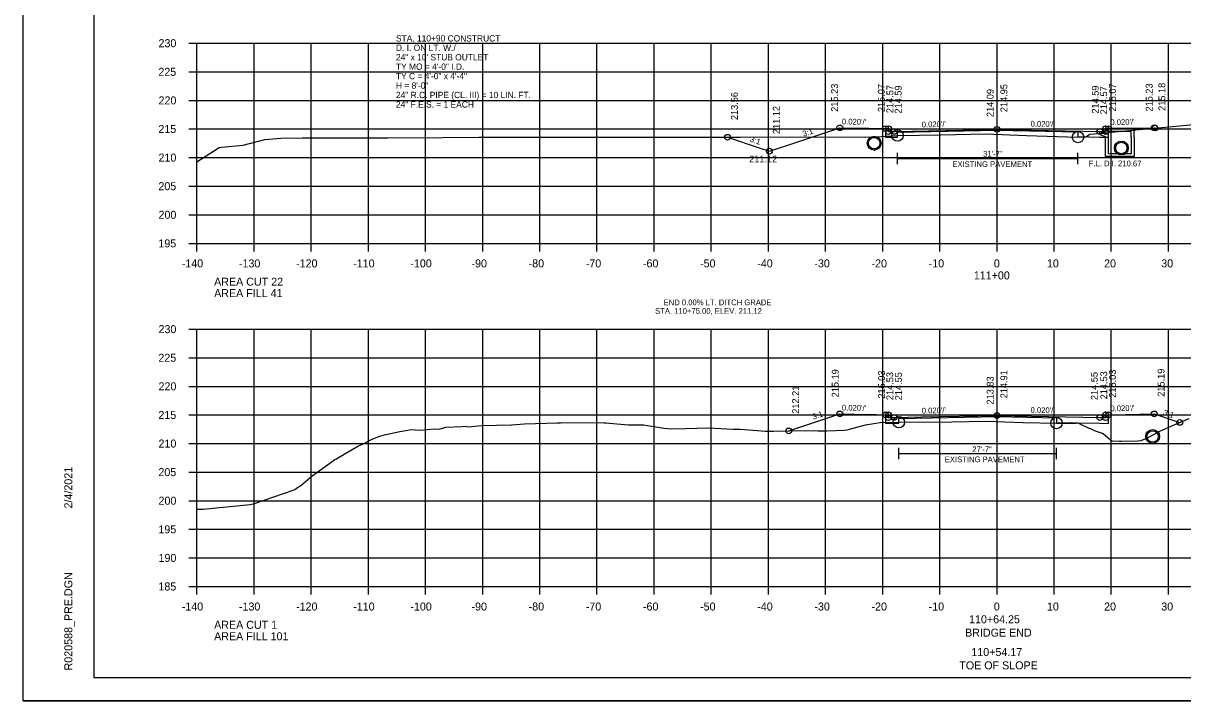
# Model space of a CAD drawing. Extents: x 1368968 to 1369915, y 377395 to 380381.
# Drawn here: x 1369581.4 to 1369784.3, y 377394.7 to 377513.2 of the extents above; entities that cross this region are included whole.
import ezdxf

# ---------------------------------------------------------------- set-up
doc = ezdxf.new("R2010")
doc.units = 0
for name, color, linetype in [('Default', 7, 'Continuous'), ('S_BORDER_NO_PLOT', 7, 'Continuous'), ('S_BREAKLINE_ANNOT', 7, 'Continuous'), ('S_BRIDGE', 7, 'Continuous'), ('S_BRIDGE_ANNOT', 7, 'Continuous'), ('S_CROSS_DRAIN', 7, 'Continuous'), ('S_CTL_TABLE', 7, 'Continuous'), ('S_CURB_ANNOT', 7, 'Continuous'), ('S_DITCHLINE_ANNOT', 7, 'Continuous'), ('S_DROP_INLET', 7, 'Continuous'), ('S_EXIST_ROW_ANNOT', 7, 'Continuous'), ('S_EXISTING_ALIGNMENT_ANNOT', 7, 'Continuous'), ('S_FENCE', 7, 'Continuous')]:
    doc.layers.add(name, color=color, linetype=linetype)

msp = doc.modelspace()

# ---------------------------------------------------------------- linework, layer by layer
at = {"layer": 'Default'}
msp.add_line((1369762.19, 377444.2), (1369762.19, 377443.37), dxfattribs=at)
at = {"layer": 'S_BORDER_NO_PLOT'}
for points in [[(1369732.27, 377494.74), (1369732.28, 377493.23), (1369733.78, 377493.26), (1369734.37, 377493.27), (1369734.37, 377494.1), (1369751.78, 377494.45), (1369765.95, 377494.17), (1369765.95, 377493.34), (1369769.78, 377493.26), (1369771.28, 377493.23), (1369771.29, 377494.74)], [(1369732.27, 377444.7), (1369732.28, 377443.19), (1369733.78, 377443.22), (1369734.61, 377443.24), (1369734.61, 377444.07), (1369751.78, 377444.41), (1369762.19, 377444.2), (1369762.19, 377443.37), (1369769.78, 377443.22), (1369771.28, 377443.19), (1369771.29, 377444.7)]]:
    msp.add_lwpolyline(points, dxfattribs=at)
at = {"layer": 'S_BREAKLINE_ANNOT'}
for p, q in [((1369610.38, 377509.68), (1369611.78, 377509.68)), ((1369611.78, 377474.68), (1369611.78, 377509.68)), ((1369610.38, 377504.68), (1369611.78, 377504.68)), ((1369610.38, 377499.68), (1369611.78, 377499.68)), ((1369610.38, 377494.68), (1369611.78, 377494.68)), ((1369610.38, 377489.68), (1369611.78, 377489.68)), ((1369610.38, 377484.68), (1369611.78, 377484.68)), ((1369610.38, 377479.68), (1369611.78, 377479.68)), ((1369610.38, 377474.68), (1369611.78, 377474.68)), ((1369611.78, 377474.68), (1369891.78, 377474.68)), ((1369611.78, 377473.28), (1369611.78, 377474.68)), ((1369621.78, 377473.28), (1369621.78, 377474.68)), ((1369631.78, 377473.28), (1369631.78, 377474.68)), ((1369641.78, 377473.28), (1369641.78, 377474.68)), ((1369651.78, 377473.28), (1369651.78, 377474.68)), ((1369661.78, 377473.28), (1369661.78, 377474.68)), ((1369671.78, 377473.28), (1369671.78, 377474.68)), ((1369681.78, 377473.28), (1369681.78, 377474.68)), ((1369691.78, 377473.28), (1369691.78, 377474.68)), ((1369701.78, 377473.28), (1369701.78, 377474.68)), ((1369711.78, 377473.28), (1369711.78, 377474.68)), ((1369721.78, 377473.28), (1369721.78, 377474.68)), ((1369731.78, 377473.28), (1369731.78, 377474.68)), ((1369741.78, 377473.28), (1369741.78, 377474.68)), ((1369751.78, 377473.28), (1369751.78, 377474.68)), ((1369761.78, 377473.28), (1369761.78, 377474.68)), ((1369771.78, 377473.28), (1369771.78, 377474.68)), ((1369781.78, 377473.28), (1369781.78, 377474.68)), ((1369610.38, 377459.68), (1369611.78, 377459.68)), ((1369611.78, 377414.68), (1369611.78, 377459.68)), ((1369610.38, 377454.68), (1369611.78, 377454.68)), ((1369610.38, 377449.68), (1369611.78, 377449.68)), ((1369610.38, 377444.68), (1369611.78, 377444.68)), ((1369610.38, 377439.68), (1369611.78, 377439.68)), ((1369610.38, 377434.68), (1369611.78, 377434.68)), ((1369610.38, 377429.68), (1369611.78, 377429.68)), ((1369610.38, 377424.68), (1369611.78, 377424.68)), ((1369610.38, 377419.68), (1369611.78, 377419.68)), ((1369610.38, 377414.68), (1369611.78, 377414.68)), ((1369611.78, 377414.68), (1369891.78, 377414.68)), ((1369611.78, 377413.28), (1369611.78, 377414.68)), ((1369621.78, 377413.28), (1369621.78, 377414.68)), ((1369631.78, 377413.28), (1369631.78, 377414.68)), ((1369641.78, 377413.28), (1369641.78, 377414.68)), ((1369651.78, 377413.28), (1369651.78, 377414.68)), ((1369661.78, 377413.28), (1369661.78, 377414.68)), ((1369671.78, 377413.28), (1369671.78, 377414.68)), ((1369681.78, 377413.28), (1369681.78, 377414.68)), ((1369691.78, 377413.28), (1369691.78, 377414.68)), ((1369701.78, 377413.28), (1369701.78, 377414.68)), ((1369711.78, 377413.28), (1369711.78, 377414.68)), ((1369721.78, 377413.28), (1369721.78, 377414.68)), ((1369731.78, 377413.28), (1369731.78, 377414.68)), ((1369741.78, 377413.28), (1369741.78, 377414.68)), ((1369751.78, 377413.28), (1369751.78, 377414.68)), ((1369761.78, 377413.28), (1369761.78, 377414.68)), ((1369771.78, 377413.28), (1369771.78, 377414.68)), ((1369781.78, 377413.28), (1369781.78, 377414.68))]:
    msp.add_line(p, q, dxfattribs=at)
at = {"layer": 'S_BRIDGE_ANNOT'}
for p, q in [((1369593.78, 377398.68), (1369593.78, 377604.14)), ((1369593.78, 377398.68), (1369593.78, 377398.68)), ((1369909.96, 377398.68), (1369593.78, 377398.68))]:
    msp.add_line(p, q, dxfattribs=at)
at = {"layer": 'S_CROSS_DRAIN'}
for p, q in [((1369734.37, 377489.54), (1369765.95, 377489.54)), ((1369734.61, 377437.92), (1369762.19, 377437.92))]:
    msp.add_line(p, q, dxfattribs=at)
at = {"layer": 'S_CTL_TABLE'}
for points in [[(1369611.78, 377488.96), (1369615.69, 377491.43), (1369616.05, 377491.49), (1369619.89, 377491.83), (1369623.65, 377492.85), (1369626.43, 377493.06), (1369630.2, 377493.16), (1369632.63, 377493.15), (1369645.18, 377493.15), (1369654.82, 377493.17), (1369661.13, 377493.23), (1369670.21, 377493.24), (1369678.08, 377493.26), (1369687.12, 377493.25), (1369692.65, 377493.27), (1369704.67, 377493.23), (1369705.31, 377493.23), (1369706.86, 377493.23), (1369717.38, 377493.29), (1369722.26, 377493.27), (1369728.66, 377493.32), (1369729.46, 377493.27), (1369730.67, 377493.32), (1369732.28, 377493.42), (1369734.37, 377493.54), (1369741.94, 377493.66), (1369749.73, 377493.86), (1369756.94, 377493.54), (1369765.95, 377493.27), (1369766.64, 377493.3), (1369767.39, 377493.33), (1369767.74, 377493.58), (1369768.01, 377493.8), (1369768.79, 377493.83), (1369779.09, 377494.82), (1369779.23, 377494.83), (1369779.37, 377494.85), (1369788.61, 377495.68)], [(1369611.78, 377428.21), (1369612.63, 377428.21), (1369612.68, 377428.21), (1369612.86, 377428.23), (1369621.08, 377428.99), (1369621.87, 377429.17), (1369628.61, 377431.53), (1369628.92, 377431.63), (1369629.35, 377431.97), (1369629.91, 377432.29), (1369631.92, 377434.04), (1369635.05, 377436.24), (1369635.9, 377436.9), (1369636.1, 377436.95), (1369637.81, 377437.97), (1369640.07, 377439.29), (1369640.62, 377439.49), (1369642.56, 377440.51), (1369643.8, 377440.99), (1369644.17, 377441.06), (1369644.6, 377441.21), (1369647.3, 377441.81), (1369648.67, 377442.03), (1369649.21, 377442.11), (1369650.84, 377442.03), (1369653.31, 377442.25), (1369654.15, 377442.22), (1369655.3, 377442.54), (1369658.2, 377442.65), (1369658.74, 377442.69), (1369659.24, 377442.62), (1369661.54, 377442.83), (1369666.84, 377442.97), (1369669.12, 377443.14), (1369674.85, 377443.28), (1369675.4, 377443.32), (1369675.72, 377443.35), (1369683.05, 377443.31), (1369683.31, 377443.31), (1369683.35, 377443.31), (1369687.26, 377442.93), (1369689.9, 377442.93), (1369693.5, 377442.37), (1369694.76, 377442.27), (1369697.27, 377442.31), (1369701.25, 377442.45), (1369705.62, 377442.21), (1369706.84, 377442.21), (1369711.28, 377441.87), (1369712.69, 377441.85), (1369718.31, 377441.93), (1369720.43, 377441.9), (1369722, 377441.89), (1369725.03, 377442), (1369725.55, 377442.08), (1369728.75, 377442.93), (1369731.68, 377443.41), (1369733.25, 377443.37), (1369734.61, 377443.4), (1369743.89, 377443.49), (1369749.88, 377443.57), (1369756.31, 377443.38), (1369762.19, 377443.26), (1369765.58, 377443.25), (1369765.95, 377443.27), (1369766.02, 377443.24), (1369766.15, 377443.16), (1369767.86, 377442.39), (1369767.93, 377442.35), (1369768.23, 377442.24), (1369768.8, 377441.98), (1369770.33, 377441.44), (1369771.24, 377440.66), (1369771.85, 377440.14), (1369772.01, 377440.15), (1369773.16, 377440.12), (1369773.58, 377440.11), (1369776.44, 377440.14), (1369777.02, 377440.2), (1369778.25, 377440.75), (1369780.28, 377441.82), (1369782.91, 377443.02), (1369785.4, 377444.06)]]:
    msp.add_lwpolyline(points, dxfattribs=at)
at = {"layer": 'S_CURB_ANNOT'}
for points in [[(1369704.63, 377493.23), (1369710.16, 377491.39), (1369711.95, 377490.8), (1369716.91, 377492.45), (1369724.27, 377494.9), (1369729.27, 377494.8), (1369732.27, 377494.74), (1369732.36, 377494.74), (1369732.77, 377494.74), (1369732.77, 377494.51), (1369732.78, 377494.24), (1369733.78, 377494.26), (1369751.78, 377494.62), (1369769.78, 377494.26), (1369770.78, 377494.24), (1369770.79, 377494.74), (1369770.89, 377494.74), (1369771.29, 377494.74), (1369774.29, 377494.8), (1369779.29, 377494.9), (1369779.36, 377494.88), (1369779.43, 377494.85)], [(1369715.34, 377441.89), (1369724.27, 377444.86), (1369729.27, 377444.76), (1369730.7, 377444.73), (1369732.27, 377444.7), (1369732.77, 377444.7), (1369732.78, 377444.2), (1369733.43, 377444.22), (1369733.78, 377444.22), (1369738.54, 377444.32), (1369751.78, 377444.58), (1369751.78, 377444.58), (1369769.78, 377444.22), (1369770.3, 377444.21), (1369770.78, 377444.2), (1369770.79, 377444.7), (1369771.29, 377444.7), (1369771.83, 377444.71), (1369774.29, 377444.76), (1369779.29, 377444.86), (1369783.75, 377443.37)]]:
    msp.add_lwpolyline(points, dxfattribs=at)
at = {"layer": 'S_DITCHLINE_ANNOT'}
for p, q in [((1369611.78, 377509.68), (1369891.78, 377509.68)), ((1369611.78, 377474.68), (1369611.78, 377509.68)), ((1369621.78, 377474.68), (1369621.78, 377509.68)), ((1369631.78, 377474.68), (1369631.78, 377509.68)), ((1369641.78, 377474.68), (1369641.78, 377509.68)), ((1369651.78, 377474.68), (1369651.78, 377509.68)), ((1369661.78, 377474.68), (1369661.78, 377509.68)), ((1369671.78, 377474.68), (1369671.78, 377509.68)), ((1369681.78, 377474.68), (1369681.78, 377509.68)), ((1369691.78, 377474.68), (1369691.78, 377509.68)), ((1369701.78, 377474.68), (1369701.78, 377509.68)), ((1369711.78, 377474.68), (1369711.78, 377509.68)), ((1369721.78, 377474.68), (1369721.78, 377509.68)), ((1369731.78, 377474.68), (1369731.78, 377509.68)), ((1369741.78, 377474.68), (1369741.78, 377509.68)), ((1369751.78, 377474.68), (1369751.78, 377509.68)), ((1369761.78, 377474.68), (1369761.78, 377509.68)), ((1369771.78, 377474.68), (1369771.78, 377509.68)), ((1369781.78, 377474.68), (1369781.78, 377509.68)), ((1369611.78, 377504.68), (1369891.78, 377504.68)), ((1369611.78, 377499.68), (1369891.78, 377499.68)), ((1369611.78, 377494.68), (1369891.78, 377494.68)), ((1369611.78, 377489.68), (1369891.78, 377489.68)), ((1369611.78, 377484.68), (1369891.78, 377484.68)), ((1369611.78, 377479.68), (1369891.78, 377479.68)), ((1369611.78, 377474.68), (1369891.78, 377474.68)), ((1369611.78, 377459.68), (1369891.78, 377459.68)), ((1369611.78, 377414.68), (1369611.78, 377459.68)), ((1369621.78, 377414.68), (1369621.78, 377459.68)), ((1369631.78, 377414.68), (1369631.78, 377459.68)), ((1369641.78, 377414.68), (1369641.78, 377459.68)), ((1369651.78, 377414.68), (1369651.78, 377459.68)), ((1369661.78, 377414.68), (1369661.78, 377459.68)), ((1369671.78, 377414.68), (1369671.78, 377459.68)), ((1369681.78, 377414.68), (1369681.78, 377459.68)), ((1369691.78, 377414.68), (1369691.78, 377459.68)), ((1369701.78, 377414.68), (1369701.78, 377459.68)), ((1369711.78, 377414.68), (1369711.78, 377459.68)), ((1369721.78, 377414.68), (1369721.78, 377459.68)), ((1369731.78, 377414.68), (1369731.78, 377459.68)), ((1369741.78, 377414.68), (1369741.78, 377459.68)), ((1369751.78, 377414.68), (1369751.78, 377459.68)), ((1369761.78, 377414.68), (1369761.78, 377459.68)), ((1369771.78, 377414.68), (1369771.78, 377459.68)), ((1369781.78, 377414.68), (1369781.78, 377459.68)), ((1369611.78, 377454.68), (1369891.78, 377454.68)), ((1369611.78, 377449.68), (1369891.78, 377449.68)), ((1369611.78, 377444.68), (1369891.78, 377444.68)), ((1369611.78, 377439.68), (1369891.78, 377439.68)), ((1369611.78, 377434.68), (1369891.78, 377434.68)), ((1369611.78, 377429.68), (1369891.78, 377429.68)), ((1369611.78, 377424.68), (1369891.78, 377424.68)), ((1369611.78, 377419.68), (1369891.78, 377419.68)), ((1369611.78, 377414.68), (1369891.78, 377414.68))]:
    msp.add_line(p, q, dxfattribs=at)
at = {"layer": 'S_DROP_INLET'}
for p, q in [((1369730.28, 377493.42), (1369730.28, 377493.26)), ((1369730.28, 377491), (1369730.28, 377490.85)), ((1369581.38, 377394.7), (1369914.71, 377394.7))]:
    msp.add_line(p, q, dxfattribs=at)
for points in [[(1369581.37, 377608.03), (1369914.71, 377608.03), (1369914.71, 377394.69), (1369581.37, 377394.69)], [(1369827.7, 377604.14), (1369827.7, 377594.26), (1369863.43, 377594.26), (1369863.43, 377591.34), (1369886.63, 377591.34), (1369886.63, 377567), (1369909.96, 377567), (1369909.96, 377398.68), (1369593.78, 377398.68), (1369593.78, 377604.14)]]:
    msp.add_lwpolyline(points, close=True, dxfattribs=at)
for centre, radius in [((1369724.27, 377494.9), 0.5), ((1369732.27, 377494.74), 0.5), ((1369732.77, 377494.74), 0.5), ((1369751.78, 377494.62), 0.5), ((1369770.79, 377494.74), 0.5), ((1369771.29, 377494.74), 0.5), ((1369779.29, 377494.9), 0.5), ((1369779.43, 377494.85), 0.5), ((1369704.63, 377493.23), 0.5), ((1369730.28, 377492.21), 1.21), ((1369732.78, 377494.24), 0.5), ((1369733.78, 377494.26), 0.5), ((1369733.78, 377494.26), 0.5), ((1369734.37, 377493.54), 1), ((1369765.95, 377493.27), 1), ((1369769.78, 377494.26), 0.5), ((1369769.78, 377494.26), 0.5), ((1369770.78, 377494.24), 0.5), ((1369711.95, 377490.8), 0.5), ((1369773.54, 377491.36), 1.21), ((1369724.27, 377444.86), 0.5), ((1369732.27, 377444.7), 0.5), ((1369732.77, 377444.7), 0.5), ((1369732.78, 377444.2), 0.5), ((1369733.78, 377444.22), 0.5), ((1369733.78, 377444.22), 0.5), ((1369734.61, 377443.4), 1), ((1369751.78, 377444.58), 0.5), ((1369769.78, 377444.22), 0.5), ((1369769.78, 377444.22), 0.5), ((1369770.78, 377444.2), 0.5), ((1369770.79, 377444.7), 0.5), ((1369771.29, 377444.7), 0.5), ((1369779.29, 377444.86), 0.5), ((1369715.34, 377441.89), 0.5), ((1369762.19, 377443.26), 1), ((1369783.75, 377443.37), 0.5), ((1369779.02, 377440.92), 1.21), ((1369779.02, 377440.92), 1)]:
    msp.add_circle(centre, radius, dxfattribs=at)
at = {"layer": 'S_EXIST_ROW_ANNOT'}
for p, q in [((1369730.28, 377493.21), (1369730.28, 377493.06)), ((1369769.78, 377494.27), (1369771.28, 377493.75)), ((1369769.78, 377493.74), (1369770.78, 377493.39)), ((1369770.78, 377493.25), (1369770.78, 377493.39)), ((1369770.94, 377494.58), (1369771.03, 377494.75)), ((1369770.94, 377494.58), (1369771.28, 377494.25)), ((1369775.78, 377494.75), (1369771.03, 377494.75)), ((1369775.28, 377494.25), (1369771.28, 377494.25)), ((1369771.28, 377493.25), (1369771.28, 377493.75)), ((1369775.28, 377493.25), (1369775.28, 377494.25)), ((1369775.78, 377493.25), (1369775.78, 377494.75)), ((1369730.28, 377491.21), (1369730.28, 377491.06)), ((1369734.37, 377488.54), (1369734.37, 377490.54)), ((1369765.95, 377488.54), (1369765.95, 377490.54)), ((1369734.61, 377436.92), (1369734.61, 377438.92)), ((1369762.19, 377436.92), (1369762.19, 377438.92))]:
    msp.add_line(p, q, dxfattribs=at)
for points in [[(1369769.78, 377493.74), (1369769.78, 377494.27)], [(1369775.78, 377493.25), (1369775.78, 377489.85), (1369773.28, 377489.85), (1369770.78, 377489.85), (1369770.78, 377493.25)], [(1369775.28, 377493.25), (1369775.28, 377490.35), (1369773.28, 377490.35), (1369771.28, 377490.35), (1369771.28, 377493.25)]]:
    msp.add_lwpolyline(points, dxfattribs=at)
for centre in [(1369730.28, 377492.21), (1369773.54, 377491.36)]:
    msp.add_circle(centre, 1, dxfattribs=at)
at = {"layer": 'S_EXISTING_ALIGNMENT_ANNOT'}
for p, q in [((1369751.78, 377493.77), (1369751.78, 377503.77)), ((1369751.78, 377443.51), (1369751.78, 377453.51))]:
    msp.add_line(p, q, dxfattribs=at)

# ---------------------------------------------------------------- texts
at = {"layer": 'Default'}
for s, p in [('STA. 110+90 CONSTRUCT', (1369646.6, 377509.98)), ('D. I. ON LT. W./', (1369646.6, 377508.33)), ('24" x 10\' STUB OUTLET ', (1369646.6, 377506.68)), ('TY MO = 4\'-0" I.D.', (1369646.6, 377505.03)), ('TY C = 4\'-0" x 4\'-4"', (1369646.6, 377503.38)), ('24" R.C. PIPE (CL. III) = 10 LIN. FT.', (1369646.6, 377500.08)), ('H = 8\'-0"', (1369646.6, 377501.73)), ('24" F.E.S. = 1 EACH', (1369646.6, 377498.43))]:
    msp.add_text(s, height=1.1, dxfattribs=at).set_placement(p)
at = {"layer": 'S_BRIDGE'}
for s, p in [('230', (1369605.05, 377508.98)), ('225', (1369605.03, 377503.98)), ('220', (1369605.05, 377498.98)), ('215', (1369605.03, 377493.98)), ('210', (1369605.05, 377488.98)), ('205', (1369605.03, 377483.98)), ('200', (1369605.05, 377478.98)), ('195', (1369605.03, 377473.98)), ('-140', (1369609.12, 377470.48)), ('-130', (1369619.12, 377470.48)), ('-120', (1369629.12, 377470.48)), ('-110', (1369639.12, 377470.48)), ('-100', (1369649.12, 377470.48)), ('-90', (1369659.82, 377470.48)), ('-80', (1369669.82, 377470.48)), ('-70', (1369679.82, 377470.48)), ('-60', (1369689.82, 377470.48)), ('-50', (1369699.82, 377470.48)), ('-40', (1369709.82, 377470.48)), ('-30', (1369719.82, 377470.48)), ('-20', (1369729.82, 377470.48)), ('-10', (1369739.82, 377470.48)), ('0', (1369751.22, 377470.48)), ('10', (1369760.52, 377470.48)), ('20', (1369770.52, 377470.48)), ('30', (1369780.52, 377470.48)), ('AREA CUT 22', (1369614.78, 377467.28)), ('111+00', (1369747.72, 377468.38)), ('AREA FILL 41', (1369614.78, 377465.28)), ('230', (1369605.05, 377458.98)), ('225', (1369605.03, 377453.98)), ('220', (1369605.05, 377448.98)), ('215', (1369605.03, 377443.98)), ('210', (1369605.05, 377438.98)), ('205', (1369605.03, 377433.98)), ('200', (1369605.05, 377428.98)), ('195', (1369605.03, 377423.98)), ('190', (1369605.05, 377418.98)), ('185', (1369605.03, 377413.98)), ('-140', (1369609.12, 377410.48)), ('-130', (1369619.12, 377410.48)), ('-120', (1369629.12, 377410.48)), ('-110', (1369639.12, 377410.48)), ('-100', (1369649.12, 377410.48)), ('-90', (1369659.82, 377410.48)), ('-80', (1369669.82, 377410.48)), ('-70', (1369679.82, 377410.48)), ('-60', (1369689.82, 377410.48)), ('-50', (1369699.82, 377410.48)), ('-40', (1369709.82, 377410.48)), ('-30', (1369719.82, 377410.48)), ('-20', (1369729.82, 377410.48)), ('-10', (1369739.82, 377410.48)), ('0', (1369751.22, 377410.48)), ('10', (1369760.52, 377410.48)), ('20', (1369770.52, 377410.48)), ('30', (1369780.52, 377410.48)), ('AREA CUT 1', (1369614.78, 377407.28)), ('110+64.25', (1369746.89, 377408.25)), ('AREA FILL 101', (1369614.78, 377405.28)), ('BRIDGE END', (1369746.19, 377405.91)), ('110+54.17', (1369747.29, 377402.52)), ('TOE OF SLOPE', (1369745.18, 377400.19))]:
    msp.add_text(s, height=1.4, dxfattribs=at).set_placement(p)
at = {"layer": 'S_BRIDGE_ANNOT'}
for s, p in [('2/4/2021', (1369589.97, 377428.32)), ('R020588_PRE.DGN', (1369589.97, 377400))]:
    msp.add_text(s, height=1.4, rotation=90, dxfattribs=at).set_placement(p)
at = {"layer": 'S_DROP_INLET'}
msp.add_text('+', height=0.1, dxfattribs=at).set_placement((1369778.97, 377439.87))
at = {"layer": 'S_EXIST_ROW_ANNOT'}
for s, height, p in [('211.12', 1.2, (1369708.41, 377488.83)), ('EXISTING PAVEMENT', 1, (1369743.96, 377488.03)), ('31\'-7"', 1, (1369749.34, 377489.84)), ('F.L. D.I. 210.67', 1, (1369767.84, 377488.16)), ('END 0.00% LT. DITCH GRADE', 1, (1369693.44, 377463.86)), ('STA. 110+75.00, ELEV. 211.12', 1, (1369691.95, 377462.36)), ('27\'-7"', 1, (1369747.46, 377438.17)), ('EXISTING PAVEMENT', 1, (1369742.64, 377436.41))]:
    msp.add_text(s, height=height, dxfattribs=at).set_placement(p)
at = {"layer": 'S_EXISTING_ALIGNMENT_ANNOT'}
for s, p in [('215.23', (1369723.95, 377497.69)), ('215.07', (1369732.13, 377497.64)), ('214.57', (1369733.64, 377497.45)), ('214.59', (1369735.09, 377497.38)), ('214.09', (1369751.18, 377496.77)), ('214.95', (1369753.58, 377497.62)), ('214.59', (1369769.58, 377497.37)), ('214.57', (1369771.05, 377497.24)), ('215.07', (1369772.59, 377497.74)), ('215.23', (1369779.01, 377497.74)), ('215.18', (1369781.23, 377497.85)), ('213.56', (1369706.43, 377496.23)), ('211.12', (1369713.75, 377493.8)), ('215.19', (1369724.07, 377447.76)), ('214.91', (1369753.58, 377447.58)), ('215.03', (1369772.59, 377447.7)), ('215.19', (1369781.09, 377447.86)), ('215.03', (1369732.18, 377447.53)), ('214.53', (1369733.63, 377447.27)), ('214.55', (1369735.14, 377447.24)), ('213.83', (1369751.18, 377446.51)), ('214.55', (1369769.4, 377447.28)), ('214.53', (1369771.06, 377447.41)), ('212.21', (1369717.14, 377444.89))]:
    msp.add_text(s, height=1.2, rotation=90, dxfattribs=at).set_placement(p)
at = {"layer": 'S_FENCE'}
for s, rotation, p in [("0.020'/'", 358.8543, (1369724.63, 377495.5)), ("0.020'/'", 1.1458, (1369738.62, 377494.96)), ("0.020'/'", 358.8542, (1369757.64, 377495.11)), ("0.020'/'", 1.1458, (1369771.63, 377495.35)), ('3:1', 341.5684, (1369708.45, 377492.49)), ('3:1', 18.4339, (1369717.95, 377493.32)), ("0.020'/'", 358.8542, (1369724.63, 377445.46)), ("0.020'/'", 1.1458, (1369771.63, 377445.31)), ('3:1', 18.4292, (1369719.64, 377443.85)), ("0.020'/'", 1.1458, (1369738.62, 377444.92)), ("0.020'/'", 358.8542, (1369757.64, 377445.07)), ('3:1', 341.5661, (1369780.78, 377444.68))]:
    msp.add_text(s, height=1, rotation=rotation, dxfattribs=at).set_placement(p)

doc.saveas('drawing.dxf')
